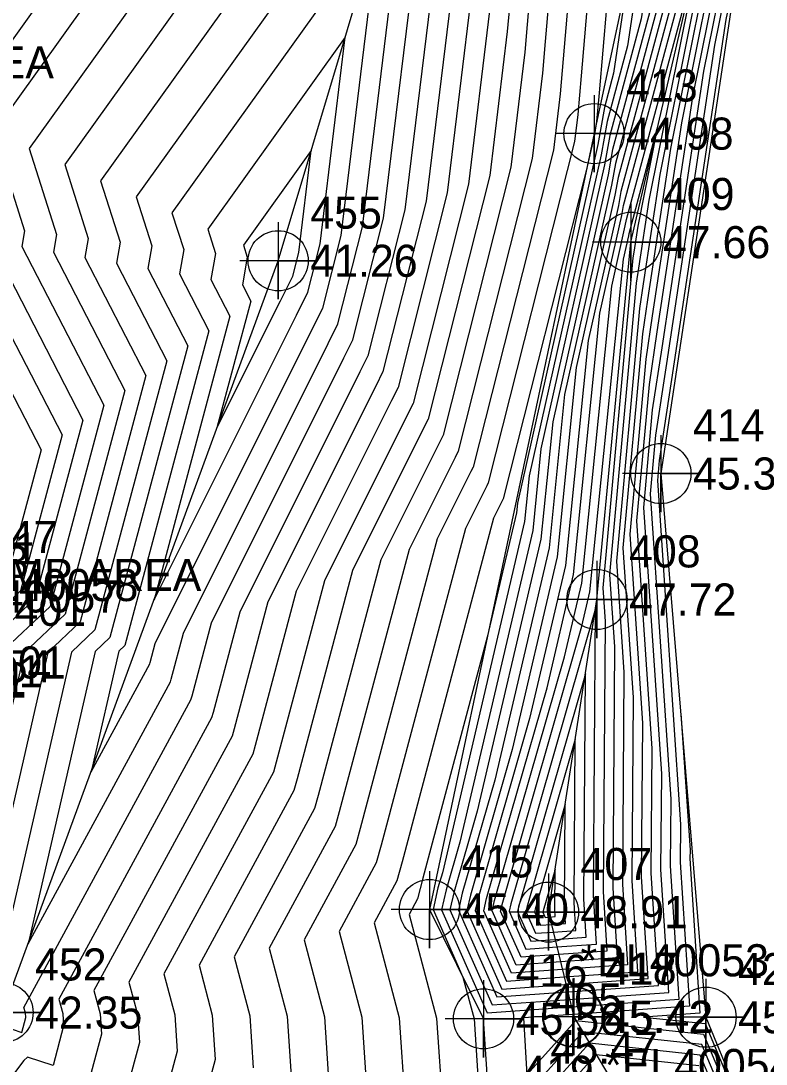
# Model space of a CAD drawing. Extents: x 2090860 to 2091277, y 159470 to 160080.
# Drawn here: x 2091069.7 to 2091127.7, y 159779.6 to 159860.8 of the extents above; entities that cross this region are included whole.
import ezdxf

# ---------------------------------------------------------------- set-up
doc = ezdxf.new("R2010")
doc.units = 0
for name, color, linetype in [('DTM Contours Major', 7, 'Continuous'), ('DTM Contours Minor', 7, 'Continuous'), ('Exist Building Cogo Elevation', 7, 'Continuous'), ('Exist DTM Breakline', 7, 'Continuous'), ('Exist DTM Breakline Cogo Comment', 7, 'Continuous'), ('Exist DTM Breakline Cogo Elevation', 7, 'Continuous'), ('Exist DTM Breakline Cogo Number', 7, 'Continuous'), ('Exist DTM Breakline Cogo Point CELL', 7, 'Continuous'), ('Exist DTM Breakline Underwater', 7, 'Continuous'), ('Exist DTM Breakline Underwater Cogo Elevation', 7, 'Continuous'), ('Exist DTM Breakline Underwater Cogo Number', 7, 'Continuous'), ('Exist DTM Breakline Underwater Cogo Point CELL', 7, 'Continuous'), ('Exist DTM Regular Point Cogo Elevation', 7, 'Continuous'), ('Exist DTM Regular Point Cogo Number', 7, 'Continuous'), ('Exist Hydro Swamp or Marsh Cogo Comment', 7, 'Continuous'), ('Exist Structure Major Deck Tunnel Box Culvert Cogo Comment', 7, 'Continuous')]:
    doc.layers.add(name, color=color, linetype=linetype)

msp = doc.modelspace()

# ---------------------------------------------------------------- linework, layer by layer
at = {"layer": 'DTM Contours Major'}
for points in [[(2091091.582, 159898.637), (2091075.464, 159895.754), (2091071.361, 159891.649), (2091065.515, 159864.769), (2091059.162, 159855.905), (2091062.527, 159845.344), (2091062.382, 159844.528), (2091071.24, 159827.424), (2091068.468, 159817.052), (2091062.553, 159811.484), (2091060.259, 159801.479), (2091046.876, 159791.945), (2091037.586, 159782.801), (2091031.987, 159764.384), (2091026.688, 159760.214), (2091021.294, 159752.688), (2091014.874, 159747.469), (2091001.671, 159730.125), (2090998.416, 159727.263), (2090990.823, 159719.668), (2090976.25, 159706.989)], [(2091099.517, 159890.851), (2091094.379, 159889.932), (2091085.334, 159880.882), (2091082.516, 159867.927), (2091070.303, 159850.886), (2091072.441, 159844.175), (2091072.201, 159842.82), (2091077.78, 159832.047), (2091073.12, 159814.614), (2091069.924, 159811.606), (2091065.116, 159790.633), (2091059.844, 159786.877), (2091043.696, 159770.983), (2091041.123, 159762.521), (2091029.056, 159753.026), (2091026.145, 159748.964), (2091013.055, 159738.321), (2091004.963, 159727.692), (2091002.968, 159725.938), (2090989.66, 159712.626), (2090981.654, 159705.661)], [(2091122.565, 159883.928), (2091121.878, 159881.704), (2091119.096, 159863.114), (2091115.786, 159850.809), (2091115.429, 159848.821), (2091111.116, 159829.605), (2091110.193, 159820.456), (2091105.233, 159799.272), (2091103.435, 159793.012), (2091103.104, 159791.575), (2091106.385, 159784.178), (2091112.426, 159784.611), (2091120.155, 159785.157), (2091119.551, 159794.732), (2091119.607, 159802.178), (2091118.207, 159822.931), (2091118.9, 159830.534), (2091119.632, 159835.369), (2091122.895, 159856.915), (2091124.672, 159865.752), (2091125.548, 159870.109), (2091128.279, 159888.173)], [(2091105.922, 159886.774), (2091104.261, 159874.343), (2091103.538, 159865.895), (2091103.449, 159864.849), (2091101.246, 159846.776), (2091097.888, 159833.505), (2091097.32, 159832.37), (2091088.926, 159815.582), (2091086.283, 159805.672), (2091086.136, 159805.119), (2091075.366, 159785.296), (2091075.848, 159783.485), (2091075.953, 159781.891), (2091074.613, 159776.904)], [(2091111.672, 159885.85), (2091110.634, 159878.082), (2091109.134, 159860.552), (2091108.948, 159858.381), (2091107.858, 159849.436), (2091102.572, 159828.552), (2091102.265, 159827.937), (2091097.718, 159818.843), (2091092.826, 159800.504), (2091092.553, 159799.481), (2091086.279, 159787.931), (2091087.501, 159783.333), (2091087.769, 159779.288)], [(2091117.422, 159884.926), (2091117.008, 159881.82), (2091114.729, 159855.209), (2091114.539, 159852.984), (2091114.358, 159851.98), (2091113.72, 159849.137), (2091107.257, 159823.599), (2091107.21, 159823.504), (2091106.51, 159822.104), (2091099.37, 159795.336), (2091098.971, 159793.843), (2091097.192, 159790.566), (2091099.154, 159783.181), (2091099.586, 159776.685)], [(2091116.5, 159845.662), (2091116.642, 159846.45), (2091123.408, 159871.606), (2091123.751, 159873.9), (2091125.877, 159880.786), (2091124.096, 159871.932), (2091119.458, 159848.869), (2091118.165, 159840.333), (2091117.875, 159838.418), (2091116.082, 159818.747), (2091116.665, 159810.095), (2091116.541, 159793.591), (2091116.938, 159787.302), (2091111.861, 159786.943), (2091107.893, 159786.659), (2091105.739, 159791.517), (2091105.956, 159792.461), (2091110.673, 159808.884), (2091112.741, 159817.715), (2091114.792, 159838.05), (2091116.5, 159845.662)], [(2091097.594, 159868.402), (2091081.444, 159845.868), (2091082.356, 159843.007), (2091082.019, 159841.112), (2091084.319, 159836.671), (2091077.773, 159812.177), (2091077.295, 159811.727), (2091075.142, 159802.335), (2091079.718, 159810.758), (2091079.74, 159810.84), (2091080.135, 159812.321), (2091092.376, 159836.804), (2091093.203, 159838.459), (2091094.634, 159844.116), (2091097.594, 159868.402)], [(2091113.721, 159789.447), (2091113.532, 159792.45), (2091113.663, 159809.968), (2091108.477, 159791.91), (2091108.373, 159791.46), (2091109.402, 159789.139), (2091111.297, 159789.275), (2091113.721, 159789.447)], [(2091127.273, 159769.18), (2091122.618, 159780.274), (2091113.978, 159781.196), (2091107.95, 159774.542)]]:
    msp.add_lwpolyline(points, dxfattribs=at)
at = {"layer": 'DTM Contours Minor'}
for points in [[(2091093.566, 159896.69), (2091080.192, 159894.298), (2091074.854, 159888.957), (2091069.765, 159865.558), (2091061.947, 159854.65), (2091065.005, 159845.052), (2091064.837, 159844.101), (2091072.875, 159828.58), (2091069.631, 159816.443), (2091064.396, 159811.515), (2091061.473, 159798.767), (2091050.118, 159790.678), (2091039.113, 159779.846), (2091034.271, 159763.918), (2091027.28, 159758.417), (2091022.507, 159751.757), (2091014.419, 159745.182), (2091002.494, 159729.516), (2090999.554, 159726.932), (2090990.532, 159717.907), (2090977.601, 159706.657)], [(2091095.549, 159894.744), (2091084.921, 159892.843), (2091078.348, 159886.266), (2091074.015, 159866.348), (2091064.733, 159853.396), (2091067.484, 159844.76), (2091067.291, 159843.674), (2091074.51, 159829.736), (2091070.794, 159815.833), (2091066.238, 159811.545), (2091062.688, 159796.056), (2091053.36, 159789.411), (2091040.641, 159776.892), (2091036.555, 159763.452), (2091027.872, 159756.62), (2091023.719, 159750.826), (2091013.964, 159742.895), (2091003.317, 159728.908), (2091000.692, 159726.601), (2090990.241, 159716.147), (2090978.952, 159706.325)], [(2091097.533, 159892.797), (2091089.65, 159891.387), (2091081.841, 159883.574), (2091078.266, 159867.137), (2091067.518, 159852.141), (2091069.963, 159844.468), (2091069.746, 159843.247), (2091076.145, 159830.892), (2091071.957, 159815.224), (2091068.081, 159811.575), (2091063.902, 159793.344), (2091056.602, 159788.144), (2091042.168, 159773.937), (2091038.839, 159762.987), (2091028.464, 159754.823), (2091024.932, 159749.895), (2091013.509, 159740.608), (2091004.14, 159728.3), (2091001.83, 159726.269), (2090989.951, 159714.386), (2090980.303, 159705.993)], [(2091129.277, 159890.946), (2091125.131, 159863.513), (2091124.96, 159862.663), (2091124.613, 159860.938), (2091120.366, 159832.887), (2091119.413, 159826.592), (2091119.27, 159825.023), (2091121.078, 159798.22), (2091121.056, 159795.303), (2091121.764, 159784.084), (2091112.708, 159783.445), (2091108.829, 159783.167), (2091109.089, 159778.735), (2091112.925, 159782.969), (2091122.861, 159781.908), (2091128.215, 159769.149)], [(2091101.501, 159888.904), (2091099.107, 159888.476), (2091088.827, 159878.19), (2091086.766, 159868.717), (2091073.088, 159849.632), (2091074.92, 159843.883), (2091074.655, 159842.393), (2091079.415, 159833.203), (2091074.283, 159814.005), (2091071.767, 159811.636), (2091066.33, 159787.921), (2091063.086, 159785.61), (2091045.223, 159768.028), (2091043.407, 159762.055), (2091029.648, 159751.229), (2091027.357, 159748.032), (2091012.6, 159736.034), (2091005.786, 159727.084), (2091004.106, 159725.607), (2090989.369, 159710.865), (2090983.005, 159705.329)], [(2091121.582, 159884.214), (2091121.409, 159883.655), (2091118.018, 159860.991), (2091115.572, 159851.898), (2091115.162, 159849.611), (2091110.197, 159827.494), (2091109.557, 159821.141), (2091103.873, 159796.869), (2091102.805, 159793.15), (2091102.446, 159791.59), (2091106.008, 159783.557), (2091112.567, 159784.028), (2091120.96, 159784.62), (2091120.303, 159795.017), (2091120.342, 159800.199), (2091118.738, 159823.977), (2091119.157, 159828.563), (2091119.999, 159834.128), (2091123.754, 159858.927), (2091124.816, 159864.207), (2091125.339, 159866.811), (2091128.778, 159889.559)], [(2091104.485, 159887.005), (2091102.668, 159873.409), (2091102.139, 159867.231), (2091102.074, 159866.465), (2091099.593, 159846.111), (2091096.716, 159834.744), (2091096.084, 159833.479), (2091086.728, 159814.767), (2091084.647, 159806.964), (2091084.531, 159806.529), (2091072.638, 159784.637), (2091072.934, 159783.522), (2091072.999, 159782.542), (2091072.174, 159779.473), (2091070.18, 159780.111), (2091069.897, 159779.847), (2091054.458, 159759.469)], [(2091107.36, 159886.543), (2091105.855, 159875.278), (2091104.937, 159864.559), (2091104.823, 159863.232), (2091102.899, 159847.441), (2091099.059, 159832.267), (2091098.556, 159831.262), (2091091.124, 159816.397), (2091087.919, 159804.38), (2091087.74, 159803.71), (2091078.094, 159785.955), (2091078.761, 159783.447), (2091078.907, 159781.24), (2091077.051, 159774.335)], [(2091123.547, 159883.643), (2091122.346, 159879.753), (2091120.174, 159865.237), (2091116, 159849.719), (2091115.697, 159848.031), (2091112.035, 159831.716), (2091110.83, 159819.77), (2091106.593, 159801.675), (2091104.066, 159792.874), (2091103.763, 159791.561), (2091106.762, 159784.798), (2091112.285, 159785.194), (2091119.351, 159785.693), (2091118.799, 159794.447), (2091118.871, 159804.157), (2091117.676, 159821.885), (2091118.644, 159832.505), (2091119.266, 159836.61), (2091122.035, 159854.904), (2091124.528, 159867.297), (2091125.757, 159873.407), (2091127.779, 159886.787)], [(2091068.988, 159782.281), (2091069.736, 159782.042), (2091070.045, 159783.193), (2091070.021, 159783.56), (2091069.91, 159783.978), (2091082.927, 159807.939), (2091083.011, 159808.256), (2091084.53, 159813.952), (2091094.848, 159834.587), (2091095.545, 159835.982), (2091097.94, 159845.446), (2091100.699, 159868.082), (2091100.74, 159868.566), (2091101.075, 159872.474), (2091102.892, 159886.076), (2091092.32, 159875.498), (2091091.017, 159869.506), (2091075.874, 159848.377), (2091077.398, 159843.591), (2091077.11, 159841.966), (2091081.05, 159834.359), (2091075.446, 159813.395), (2091073.609, 159811.666), (2091067.544, 159785.21)], [(2091108.797, 159886.312), (2091107.448, 159876.212), (2091106.336, 159863.224), (2091106.198, 159861.615), (2091104.552, 159848.106), (2091100.23, 159831.029), (2091099.793, 159830.154), (2091093.322, 159817.212), (2091089.555, 159803.088), (2091089.345, 159802.3), (2091080.823, 159786.614), (2091081.674, 159783.409), (2091081.861, 159780.589), (2091079.489, 159771.767)], [(2091110.235, 159886.081), (2091109.041, 159877.147), (2091107.735, 159861.888), (2091107.573, 159859.998), (2091106.205, 159848.771), (2091101.401, 159829.79), (2091101.029, 159829.046), (2091095.52, 159818.028), (2091091.191, 159801.796), (2091090.949, 159800.891), (2091083.551, 159787.272), (2091084.588, 159783.371), (2091084.815, 159779.939), (2091081.928, 159769.198)], [(2091113.11, 159885.619), (2091112.228, 159879.016), (2091110.532, 159859.216), (2091110.323, 159856.764), (2091109.511, 159850.101), (2091103.743, 159827.314), (2091103.501, 159826.829), (2091099.916, 159819.658), (2091094.462, 159799.212), (2091094.158, 159798.071), (2091089.007, 159788.59), (2091090.414, 159783.295), (2091090.724, 159778.637)], [(2091114.547, 159885.388), (2091113.821, 159879.951), (2091111.931, 159857.881), (2091111.697, 159855.147), (2091111.163, 159850.766), (2091104.915, 159826.075), (2091104.737, 159825.721), (2091102.114, 159820.473), (2091096.098, 159797.92), (2091095.762, 159796.662), (2091091.735, 159789.249), (2091093.328, 159783.257), (2091093.678, 159777.986)], [(2091115.985, 159885.157), (2091115.414, 159880.886), (2091113.33, 159856.545), (2091113.072, 159853.531), (2091112.816, 159851.431), (2091106.086, 159824.837), (2091105.974, 159824.612), (2091104.312, 159821.288), (2091097.734, 159796.628), (2091097.367, 159795.252), (2091094.463, 159789.908), (2091096.241, 159783.219), (2091096.632, 159777.335)], [(2091124.53, 159883.357), (2091122.815, 159877.802), (2091121.252, 159867.36), (2091116.214, 159848.629), (2091115.965, 159847.242), (2091112.954, 159833.828), (2091111.467, 159819.085), (2091107.953, 159804.078), (2091104.696, 159792.737), (2091104.421, 159791.546), (2091107.139, 159785.418), (2091112.144, 159785.777), (2091118.547, 159786.229), (2091118.046, 159794.162), (2091118.136, 159806.137), (2091117.144, 159820.839), (2091118.388, 159834.476), (2091118.899, 159837.851), (2091121.176, 159852.892), (2091124.384, 159868.842), (2091125.966, 159876.706), (2091127.28, 159885.4)], [(2091118.86, 159884.695), (2091118.601, 159882.755), (2091117.059, 159864.743), (2091115.862, 159856.745), (2091115.144, 159854.078), (2091114.626, 159851.19), (2091108.36, 159823.271), (2091108.283, 159822.511), (2091106.013, 159812.818), (2091101.006, 159794.044), (2091100.576, 159792.433), (2091099.92, 159791.225), (2091102.068, 159783.144), (2091102.54, 159776.034)], [(2091120.297, 159884.463), (2091120.194, 159883.689), (2091119.579, 159876.502), (2091116.94, 159858.868), (2091115.358, 159852.988), (2091114.894, 159850.4), (2091109.279, 159825.383), (2091108.92, 159821.826), (2091102.513, 159794.466), (2091102.175, 159793.287), (2091101.787, 159791.604), (2091104.122, 159786.339), (2091104.981, 159783.106), (2091105.494, 159775.383)], [(2091125.512, 159883.072), (2091123.283, 159875.851), (2091122.33, 159869.483), (2091116.428, 159847.539), (2091116.233, 159846.452), (2091113.873, 159835.939), (2091112.104, 159818.4), (2091109.313, 159806.481), (2091105.326, 159792.599), (2091105.08, 159791.532), (2091107.516, 159786.038), (2091112.003, 159786.36), (2091117.743, 159786.765), (2091117.294, 159793.876), (2091117.401, 159808.116), (2091116.613, 159819.793), (2091118.132, 159836.447), (2091118.532, 159839.092), (2091120.317, 159850.88), (2091124.24, 159870.387), (2091126.174, 159880.004), (2091126.78, 159884.014)], [(2091096.287, 159844.781), (2091099.324, 159869.699), (2091099.341, 159869.902), (2091099.482, 159871.539), (2091100.243, 159877.239), (2091095.813, 159872.807), (2091095.267, 159870.296), (2091078.659, 159847.122), (2091079.877, 159843.299), (2091079.564, 159841.539), (2091082.685, 159835.515), (2091076.609, 159812.786), (2091075.452, 159811.697), (2091070.236, 159788.941), (2091081.322, 159809.348), (2091081.375, 159809.548), (2091082.333, 159813.136), (2091093.612, 159835.695), (2091094.374, 159837.22), (2091096.287, 159844.781)], [(2091116.768, 159844.872), (2091116.856, 159845.36), (2091122.571, 159866.61), (2091118.598, 159846.857), (2091117.799, 159841.574), (2091117.619, 159840.389), (2091115.55, 159817.701), (2091115.93, 159812.075), (2091115.789, 159793.306), (2091116.134, 159787.838), (2091111.72, 159787.526), (2091108.271, 159787.279), (2091106.397, 159791.503), (2091106.586, 159792.323), (2091112.033, 159811.287), (2091113.378, 159817.03), (2091115.711, 159840.161), (2091116.768, 159844.872)], [(2091094.945, 159859.565), (2091084.229, 159844.613), (2091084.834, 159842.715), (2091084.474, 159840.685), (2091085.954, 159837.826), (2091080.048, 159815.728), (2091091.139, 159837.912), (2091092.032, 159839.697), (2091092.982, 159843.45), (2091094.945, 159859.565)], [(2091117.036, 159844.083), (2091117.07, 159844.27), (2091119.266, 159852.435), (2091117.739, 159844.845), (2091117.432, 159842.816), (2091117.363, 159842.36), (2091115.019, 159816.656), (2091115.194, 159814.054), (2091115.037, 159793.021), (2091115.33, 159788.374), (2091111.579, 159788.109), (2091108.648, 159787.899), (2091107.056, 159791.489), (2091107.217, 159792.186), (2091113.393, 159813.689), (2091114.014, 159816.345), (2091116.63, 159842.273), (2091117.036, 159844.083)], [(2091092.297, 159850.728), (2091087.015, 159843.359), (2091087.313, 159842.423), (2091086.928, 159840.258), (2091087.589, 159838.982), (2091084.953, 159829.12), (2091089.903, 159839.02), (2091090.86, 159840.935), (2091091.329, 159842.785), (2091092.297, 159850.728)], [(2091114.526, 159788.91), (2091114.284, 159792.735), (2091114.452, 159815.045), (2091107.847, 159792.048), (2091107.714, 159791.474), (2091109.025, 159788.519), (2091111.438, 159788.692), (2091114.526, 159788.91)], [(2091121.095, 159806.882), (2091121.813, 159796.24), (2091121.808, 159795.588), (2091122.568, 159783.548), (2091118.178, 159783.238), (2091122.983, 159782.725), (2091128.686, 159769.134), (2091127.192, 159763.272), (2091128.656, 159758.211), (2091137.8, 159757.8), (2091140, 159753.448), (2091156.79, 159753.04)], [(2091112.917, 159789.983), (2091112.779, 159792.165), (2091112.875, 159804.891), (2091109.107, 159791.773), (2091109.032, 159791.445), (2091109.779, 159789.76), (2091111.156, 159789.858), (2091112.917, 159789.983)], [(2091112.113, 159790.519), (2091112.027, 159791.879), (2091112.087, 159799.814), (2091109.737, 159791.635), (2091109.69, 159791.431), (2091110.156, 159790.38), (2091111.015, 159790.441), (2091112.113, 159790.519)], [(2091111.309, 159791.055), (2091111.275, 159791.594), (2091111.298, 159794.737), (2091110.368, 159791.497), (2091110.349, 159791.416), (2091110.534, 159791), (2091110.874, 159791.025), (2091111.309, 159791.055)], [(2091127.744, 159769.165), (2091122.74, 159781.091), (2091113.452, 159782.082), (2091106.971, 159774.929)], [(2091108.929, 159774.155), (2091114.505, 159780.309), (2091122.497, 159779.456)]]:
    msp.add_lwpolyline(points, dxfattribs=at)
at = {"layer": 'Exist DTM Breakline'}
msp.add_line((2091123.057, 159783.222), (2091128.861, 159769.128), dxfattribs=at)
for points in [[(2091129.505, 159891.578), (2091119.546, 159825.567), (2091123.057, 159783.222)], [(2091121.252, 159884.31), (2091114.337, 159852.043), (2091101.513, 159791.61), (2091105.727, 159783.096)], [(2091110.781, 159791.407), (2091114.562, 159815.756), (2091117.203, 159843.59), (2091126.353, 159882.827)], [(2091110.781, 159791.407), (2091112.754, 159783.256), (2091120.998, 159769.385), (2091116.8, 159758.801)], [(2091104.06, 159746.702), (2091106.238, 159775.219), (2091105.727, 159783.096)]]:
    msp.add_lwpolyline(points, dxfattribs=at)
at = {"layer": 'Exist DTM Breakline Cogo Point CELL'}
for points in [[(2091114.337, 159855.043), (2091114.337, 159849.043), (2091114.337, 159852.043), (2091117.337, 159852.043), (2091111.337, 159852.043)], [(2091117.203, 159846.59), (2091117.203, 159840.59), (2091117.203, 159843.59), (2091120.203, 159843.59), (2091114.203, 159843.59)], [(2091119.546, 159828.567), (2091119.546, 159822.567), (2091119.546, 159825.567), (2091122.546, 159825.567), (2091116.546, 159825.567)], [(2091114.562, 159818.756), (2091114.562, 159812.756), (2091114.562, 159815.756), (2091117.562, 159815.756), (2091111.562, 159815.756)], [(2091101.513, 159794.61), (2091101.513, 159788.61), (2091101.513, 159791.61), (2091104.513, 159791.61), (2091098.513, 159791.61)], [(2091110.781, 159794.407), (2091110.781, 159788.407), (2091110.781, 159791.407), (2091113.781, 159791.407), (2091107.781, 159791.407)], [(2091105.727, 159786.096), (2091105.727, 159780.096), (2091105.727, 159783.096), (2091108.727, 159783.096), (2091102.727, 159783.096)], [(2091112.688, 159786.25), (2091112.688, 159780.25), (2091112.688, 159783.25), (2091115.688, 159783.25), (2091109.688, 159783.25)], [(2091112.754, 159786.256), (2091112.754, 159780.256), (2091112.754, 159783.256), (2091115.754, 159783.256), (2091109.754, 159783.256)], [(2091123.057, 159786.222), (2091123.057, 159780.222), (2091123.057, 159783.222), (2091126.057, 159783.222), (2091120.057, 159783.222)]]:
    msp.add_lwpolyline(points, dxfattribs=at)
for centre in [(2091114.337, 159852.043), (2091117.203, 159843.59), (2091119.546, 159825.567), (2091114.562, 159815.756), (2091101.513, 159791.61), (2091110.781, 159791.407), (2091112.688, 159783.25), (2091112.754, 159783.256), (2091105.727, 159783.096), (2091123.057, 159783.222)]:
    msp.add_circle(centre, 2.344, dxfattribs=at)
at = {"layer": 'Exist DTM Breakline Underwater'}
msp.add_lwpolyline([(2090988.242, 159704.041), (2091010.175, 159723.841), (2091048.889, 159760.937), (2091068.273, 159783.583), (2091089.722, 159842.139), (2091103.231, 159887.207)], dxfattribs=at)
at = {"layer": 'Exist DTM Breakline Underwater Cogo Point CELL'}
for points in [[(2091089.722, 159845.139), (2091089.722, 159839.139), (2091089.722, 159842.139), (2091092.722, 159842.139), (2091086.722, 159842.139)], [(2091068.273, 159786.583), (2091068.273, 159780.583), (2091068.273, 159783.583), (2091071.273, 159783.583), (2091065.273, 159783.583)]]:
    msp.add_lwpolyline(points, dxfattribs=at)
for centre in [(2091089.722, 159842.139), (2091068.273, 159783.583)]:
    msp.add_circle(centre, 2.344, dxfattribs=at)

# ---------------------------------------------------------------- texts
at = {"layer": 'Exist Building Cogo Elevation'}
for s, p in [('46.53', (2091061.926, 159817.454)), ('*EL3401', (2091061.926, 159813.704)), ('*EL3401', (2091060.343, 159809.603)), ('*BL3401', (2091057.271, 159808.269)), ('*BL3401', (2091058.547, 159808.919))]:
    msp.add_text(s, height=2.5, dxfattribs=at).set_placement(p)
at = {"layer": 'Exist DTM Breakline Cogo Comment'}
for s, p in [('SWAMP AREA', (2091049.585, 159856.345)), ('*BL40058', (2091064.134, 159815.633)), ('*BL40057', (2091062.643, 159814.743)), ('*BL40054', (2091057.351, 159809.302)), ('*BL40053', (2091113.281, 159786.407)), ('*EL40054', (2091115.188, 159778.25))]:
    msp.add_text(s, height=2.5, dxfattribs=at).set_placement(p)
at = {"layer": 'Exist DTM Breakline Cogo Elevation'}
for s, p in [('44.98', (2091116.837, 159850.793)), ('47.66', (2091119.703, 159842.34)), ('45.37', (2091122.046, 159824.317)), ('45.47', (2091064.134, 159819.383)), ('46.51', (2091062.643, 159818.493)), ('47.72', (2091117.062, 159814.506)), ('45.40', (2091104.013, 159790.36)), ('48.91', (2091113.281, 159790.157)), ('45.56', (2091108.227, 159781.846)), ('45.42', (2091115.188, 159782)), ('45.42', (2091115.254, 159782.006)), ('45.10', (2091125.557, 159781.972))]:
    msp.add_text(s, height=2.5, dxfattribs=at).set_placement(p)
at = {"layer": 'Exist DTM Breakline Cogo Number'}
for s, p in [('413', (2091116.837, 159854.543)), ('409', (2091119.703, 159846.09)), ('414', (2091122.046, 159828.067)), ('408', (2091117.062, 159818.256)), ('415', (2091104.013, 159794.11)), ('407', (2091113.281, 159793.907)), ('416', (2091108.227, 159785.596)), ('418', (2091115.188, 159785.75)), ('417', (2091115.254, 159785.756)), ('420', (2091125.557, 159785.722)), ('419', (2091108.738, 159777.719))]:
    msp.add_text(s, height=2.5, dxfattribs=at).set_placement(p)
at = {"layer": 'Exist DTM Breakline Underwater Cogo Elevation'}
for s, p in [('41.26', (2091092.222, 159840.889)), ('42.35', (2091070.773, 159782.333))]:
    msp.add_text(s, height=2.5, dxfattribs=at).set_placement(p)
at = {"layer": 'Exist DTM Breakline Underwater Cogo Number'}
for s, p in [('455', (2091092.222, 159844.639)), ('452', (2091070.773, 159786.083))]:
    msp.add_text(s, height=2.5, dxfattribs=at).set_placement(p)
at = {"layer": 'Exist DTM Regular Point Cogo Elevation'}
msp.add_text('45.47', height=2.5, dxfattribs=at).set_placement((2091110.941, 159779.607))
at = {"layer": 'Exist DTM Regular Point Cogo Number'}
msp.add_text('405', height=2.5, dxfattribs=at).set_placement((2091110.941, 159783.357))
at = {"layer": 'Exist Hydro Swamp or Marsh Cogo Comment'}
msp.add_text('SWAMP AREA', height=2.5, dxfattribs=at).set_placement((2091061.071, 159816.422))
at = {"layer": 'Exist Structure Major Deck Tunnel Box Culvert Cogo Comment'}
msp.add_text('*CL31011', height=2.5, dxfattribs=at).set_placement((2091055.243, 159808.103))

doc.saveas('drawing.dxf')
